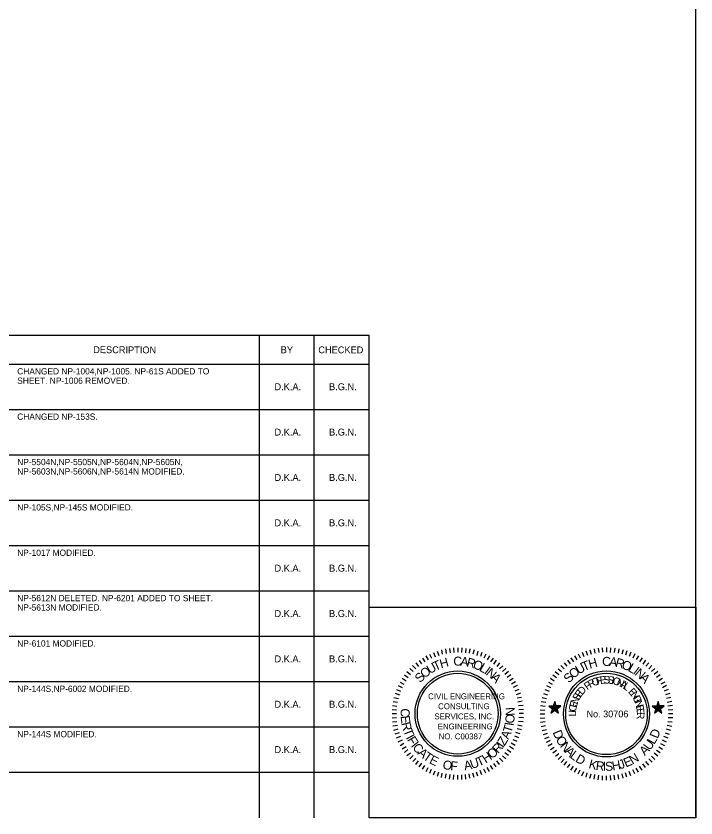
# Model space of a CAD drawing. Extents: x 261099 to 262774, y 322332 to 323393.
# Drawn here: x 262340 to 262774, y 322332 to 322845 of the extents above; entities that cross this region are included whole.
import ezdxf

# ---------------------------------------------------------------- set-up
doc = ezdxf.new("R2010")
doc.units = 0
for name, color, linetype in [('Level 1', 7, 'Continuous'), ('Level 3', 7, 'Continuous'), ('RD_SHT_SEAL_KA', 7, 'Continuous'), ('RD_SHT_TX', 7, 'Continuous')]:
    doc.layers.add(name, color=color, linetype=linetype)

msp = doc.modelspace()

# ---------------------------------------------------------------- linework, layer by layer
at = {"layer": 'Level 1'}
msp.add_lwpolyline([(262565.22, 322466.62), (262774.17, 322466.62), (262774.17, 322331.93), (262565.22, 322331.93)], close=True, dxfattribs=at)
at = {"layer": 'Level 3'}
msp.add_line((262774.17, 322332.83), (262774.17, 323381.93), dxfattribs=at)
at = {"layer": 'RD_SHT_SEAL_KA'}
for p, q in [((262619.3, 322440.71), (262619.44, 322437.75)), ((262621.93, 322440.78), (262621.92, 322437.87)), ((262624.55, 322440.66), (262624.36, 322437.77)), ((262627.12, 322440.39), (262626.8, 322437.59)), ((262711.74, 322440.51), (262712.06, 322437.7)), ((262714.33, 322440.78), (262714.49, 322437.92)), ((262717.03, 322440.84), (262716.97, 322438.03)), ((262719.57, 322440.78), (262719.4, 322437.81)), ((262722.32, 322440.57), (262721.94, 322437.65)), ((262601.58, 322435.55), (262602.98, 322433.01)), ((262603.97, 322436.67), (262605.22, 322434.11)), ((262606.44, 322437.8), (262607.49, 322435.06)), ((262608.87, 322438.62), (262609.77, 322435.87)), ((262611.45, 322439.39), (262612.06, 322436.6)), ((262614.06, 322440.02), (262614.53, 322437.14)), ((262616.7, 322440.35), (262617.04, 322437.56)), ((262629.74, 322440.01), (262629.26, 322437.27)), ((262632.35, 322439.37), (262631.62, 322436.56)), ((262634.86, 322438.67), (262634.02, 322435.89)), ((262637.32, 322437.75), (262636.39, 322435.1)), ((262639.8, 322436.68), (262638.6, 322434.04)), ((262642.14, 322435.53), (262640.7, 322433.07)), ((262696.51, 322435.65), (262697.97, 322433.06)), ((262698.94, 322436.84), (262700.18, 322434.25)), ((262701.37, 322437.92), (262702.45, 322435.17)), ((262703.85, 322438.78), (262704.82, 322436.08)), ((262706.39, 322439.54), (262707.14, 322436.73)), ((262709.09, 322440.13), (262709.57, 322437.22)), ((262724.97, 322440.13), (262724.42, 322437.32)), ((262727.56, 322439.54), (262726.8, 322436.73)), ((262730.09, 322438.84), (262729.23, 322436.03)), ((262732.63, 322437.92), (262731.55, 322435.22)), ((262735.01, 322436.84), (262733.77, 322434.19)), ((262737.39, 322435.65), (262736.04, 322433.17)), ((262595.12, 322431.17), (262596.91, 322428.79)), ((262597.17, 322432.69), (262598.79, 322430.44)), ((262599.41, 322434.13), (262600.9, 322431.78)), ((262644.48, 322434.1), (262642.88, 322431.71)), ((262646.58, 322432.8), (262644.88, 322430.35)), ((262648.66, 322431.05), (262646.93, 322428.82)), ((262689.92, 322431.17), (262691.75, 322428.9)), ((262692.02, 322432.74), (262693.75, 322430.42)), ((262694.29, 322434.25), (262695.8, 322431.87)), ((262739.76, 322434.25), (262738.19, 322431.82)), ((262741.92, 322432.79), (262740.25, 322430.36)), ((262744.03, 322431.17), (262742.19, 322428.96)), ((262589.39, 322425.5), (262591.71, 322423.63)), ((262591.27, 322427.41), (262593.42, 322425.48)), ((262593.04, 322429.34), (262595.13, 322427.26)), ((262650.67, 322429.29), (262648.69, 322427.26)), ((262652.65, 322427.49), (262650.44, 322425.5)), ((262654.27, 322425.5), (262652.09, 322423.62)), ((262684.25, 322425.5), (262686.52, 322423.67)), ((262686.09, 322427.39), (262688.19, 322425.5)), ((262687.87, 322429.39), (262689.97, 322427.23)), ((262746.02, 322429.39), (262744.14, 322427.28)), ((262747.97, 322427.5), (262745.81, 322425.5)), ((262749.7, 322425.5), (262747.48, 322423.67)), ((262586.35, 322421.24), (262588.85, 322419.69)), ((262587.87, 322423.37), (262590.13, 322421.68)), ((262655.92, 322423.36), (262653.56, 322421.68)), ((262657.42, 322421.2), (262655, 322419.7)), ((262681.17, 322421.23), (262683.65, 322419.62)), ((262682.63, 322423.39), (262685.06, 322421.67)), ((262751.26, 322423.39), (262748.99, 322421.72)), ((262752.83, 322421.18), (262750.4, 322419.67)), ((262583.84, 322416.57), (262586.41, 322415.37)), ((262585.08, 322418.85), (262587.44, 322417.54)), ((262658.85, 322418.96), (262656.25, 322417.47)), ((262659.9, 322416.55), (262657.44, 322415.35)), ((262678.58, 322416.54), (262681.17, 322415.29)), ((262679.82, 322418.86), (262682.36, 322417.51)), ((262754.18, 322418.86), (262751.69, 322417.45)), ((262755.31, 322416.54), (262752.77, 322415.24)), ((262581.85, 322411.63), (262584.68, 322410.76)), ((262582.8, 322414.13), (262585.4, 322413.04)), ((262660.94, 322414.15), (262658.32, 322413.08)), ((262661.93, 322411.67), (262659.17, 322410.76)), ((262676.64, 322411.52), (262679.39, 322410.65)), ((262677.55, 322414.05), (262680.25, 322412.97)), ((262756.45, 322414.11), (262753.75, 322413.02)), ((262757.37, 322411.57), (262754.61, 322410.65)), ((262580.56, 322406.48), (262583.42, 322405.98)), ((262581.17, 322409.05), (262583.95, 322408.28)), ((262662.66, 322409.04), (262659.83, 322408.46)), ((262663.16, 322406.53), (262660.37, 322405.92)), ((262675.34, 322406.38), (262678.2, 322405.9)), ((262675.88, 322408.97), (262678.74, 322408.27)), ((262758.12, 322409.03), (262755.26, 322408.33)), ((262758.72, 322406.44), (262755.8, 322405.84)), ((262579.96, 322401.19), (262582.81, 322401.02)), ((262580.14, 322403.89), (262583.06, 322403.48)), ((262663.71, 322403.92), (262660.71, 322403.54)), ((262663.9, 322401.26), (262660.98, 322401.08)), ((262674.69, 322401.09), (262677.55, 322400.93)), ((262674.91, 322403.74), (262677.77, 322403.42)), ((262759.15, 322403.74), (262756.23, 322403.47)), ((262759.31, 322401.09), (262756.45, 322400.93)), ((262579.94, 322395.97), (262582.82, 322396.18)), ((262579.97, 322398.66), (262582.73, 322398.63)), ((262663.89, 322395.97), (262661, 322396.17)), ((262663.88, 322398.69), (262661.13, 322398.64)), ((262674.64, 322398.44), (262677.5, 322398.44)), ((262674.64, 322395.8), (262677.5, 322395.96)), ((262759.31, 322395.85), (262756.45, 322396.02)), ((262759.42, 322398.44), (262756.55, 322398.5)), ((262580.19, 322393.39), (262583.05, 322393.68)), ((262580.52, 322390.75), (262583.36, 322391.26)), ((262663.17, 322390.7), (262660.35, 322391.25)), ((262663.66, 322393.37), (262660.71, 322393.67)), ((262674.91, 322393.1), (262677.82, 322393.53)), ((262675.29, 322390.51), (262678.09, 322390.99)), ((262758.72, 322390.51), (262755.8, 322391.05)), ((262759.04, 322393.15), (262756.18, 322393.42)), ((262581.18, 322388.12), (262583.88, 322388.87)), ((262581.93, 322385.68), (262584.62, 322386.5)), ((262582.78, 322383.1), (262585.5, 322384.23)), ((262660.98, 322383.21), (262658.32, 322384.21)), ((262661.9, 322385.67), (262659.11, 322386.51)), ((262662.67, 322388.18), (262659.86, 322388.91)), ((262675.93, 322387.86), (262678.69, 322388.57)), ((262676.69, 322385.38), (262679.39, 322386.24)), ((262757.31, 322385.38), (262754.61, 322386.24)), ((262758.12, 322387.92), (262755.26, 322388.67)), ((262583.83, 322380.63), (262586.53, 322381.97)), ((262585.09, 322378.33), (262587.51, 322379.82)), ((262658.72, 322378.34), (262656.16, 322379.73)), ((262659.94, 322380.77), (262657.41, 322381.94)), ((262677.5, 322382.84), (262680.25, 322383.87)), ((262678.63, 322380.36), (262681.22, 322381.65)), ((262679.77, 322377.98), (262682.36, 322379.44)), ((262754.18, 322378.03), (262751.64, 322379.38)), ((262755.37, 322380.36), (262752.77, 322381.65)), ((262756.45, 322382.89), (262753.69, 322383.92)), ((262586.41, 322376.11), (262588.86, 322377.65)), ((262587.93, 322373.8), (262590.12, 322375.61)), ((262655.9, 322373.78), (262653.59, 322375.58)), ((262657.46, 322375.95), (262654.94, 322377.57)), ((262681.22, 322375.71), (262683.55, 322377.22)), ((262682.68, 322373.5), (262685, 322375.22)), ((262751.32, 322373.5), (262748.99, 322375.17)), ((262752.83, 322375.66), (262750.4, 322377.17)), ((262589.44, 322371.83), (262591.68, 322373.6)), ((262591.25, 322369.82), (262593.43, 322371.77)), ((262593.12, 322367.97), (262595.14, 322370.05)), ((262650.71, 322367.95), (262648.66, 322370.08)), ((262652.56, 322369.82), (262650.49, 322371.76)), ((262654.36, 322371.8), (262652.09, 322373.56)), ((262684.3, 322371.44), (262686.57, 322373.23)), ((262686.09, 322369.39), (262688.19, 322371.39)), ((262688.03, 322367.45), (262689.92, 322369.61)), ((262746.08, 322367.5), (262744.08, 322369.67)), ((262747.92, 322369.39), (262745.86, 322371.39)), ((262749.75, 322371.44), (262747.48, 322373.28)), ((262595.14, 322366.14), (262596.87, 322368.37)), ((262597.2, 322364.61), (262598.89, 322366.87)), ((262599.32, 322363.09), (262600.88, 322365.52)), ((262601.65, 322361.74), (262603.02, 322364.18)), ((262642.17, 322361.74), (262640.83, 322364.18)), ((262644.38, 322363.14), (262642.9, 322365.49)), ((262646.58, 322364.61), (262644.93, 322366.82)), ((262648.63, 322366.13), (262646.93, 322368.37)), ((262689.97, 322365.77), (262691.75, 322367.94)), ((262692.08, 322364.16), (262693.81, 322366.42)), ((262694.24, 322362.59), (262695.8, 322365.07)), ((262696.56, 322361.29), (262697.97, 322363.78)), ((262737.39, 322361.29), (262736.04, 322363.78)), ((262739.71, 322362.59), (262738.19, 322365.02)), ((262741.97, 322364.16), (262740.3, 322366.48)), ((262743.97, 322365.72), (262742.19, 322367.94)), ((262604, 322360.51), (262605.19, 322363.23)), ((262606.4, 322359.5), (262607.49, 322362.1)), ((262608.9, 322358.55), (262609.75, 322361.34)), ((262611.48, 322357.87), (262612.07, 322360.66)), ((262614.02, 322357.29), (262614.51, 322360.15)), ((262616.61, 322356.8), (262617.03, 322359.72)), ((262619.31, 322356.61), (262619.47, 322359.54)), ((262621.93, 322356.57), (262621.91, 322359.36)), ((262624.6, 322356.6), (262624.43, 322359.52)), ((262627.11, 322356.84), (262626.78, 322359.74)), ((262629.7, 322357.28), (262629.28, 322360.06)), ((262632.34, 322357.87), (262631.66, 322360.65)), ((262634.86, 322358.56), (262634, 322361.28)), ((262637.39, 322359.51), (262636.31, 322362.2)), ((262639.86, 322360.56), (262638.6, 322363.2)), ((262698.99, 322360.05), (262700.18, 322362.7)), ((262701.31, 322358.97), (262702.5, 322361.67)), ((262703.9, 322358.11), (262704.72, 322360.86)), ((262706.44, 322357.3), (262707.09, 322360.16)), ((262709.04, 322356.76), (262709.57, 322359.67)), ((262711.68, 322356.38), (262712.06, 322359.24)), ((262714.38, 322356.11), (262714.54, 322358.97)), ((262717.03, 322356.06), (262717.03, 322358.92)), ((262719.67, 322356), (262719.51, 322359.02)), ((262722.27, 322356.38), (262721.94, 322359.24)), ((262724.91, 322356.76), (262724.42, 322359.62)), ((262727.56, 322357.35), (262726.91, 322360.16)), ((262730.09, 322358.11), (262729.23, 322360.81)), ((262732.63, 322358.97), (262731.55, 322361.67)), ((262735.12, 322360.11), (262733.87, 322362.7))]:
    msp.add_line(p, q, dxfattribs=at)
for points in [[(262683.92, 322406.38), (262683.01, 322403.52), (262680.09, 322403.52), (262682.47, 322401.74), (262681.49, 322399.04), (262683.98, 322400.77), (262686.3, 322399.04), (262685.38, 322401.79), (262687.76, 322403.57), (262684.84, 322403.57)], [(262683.87, 322405.95), (262683.12, 322403.47), (262680.42, 322403.47), (262682.52, 322401.85), (262681.77, 322399.31), (262683.87, 322400.93), (262686.03, 322399.31), (262685.22, 322401.9), (262687.44, 322403.42), (262684.79, 322403.47)], [(262683.98, 322405.57), (262683.12, 322403.31), (262680.79, 322403.31), (262682.74, 322401.9), (262682.04, 322399.63), (262683.92, 322401.04), (262685.87, 322399.58), (262685.06, 322401.96), (262687.06, 322403.25), (262684.68, 322403.31)], [(262683.98, 322405.19), (262683.22, 322403.2), (262681.17, 322403.14), (262682.9, 322401.96), (262682.25, 322399.96), (262683.87, 322401.2), (262685.65, 322399.96), (262685.06, 322401.96), (262686.68, 322403.25), (262684.57, 322403.14)], [(262683.92, 322404.82), (262683.39, 322403.09), (262681.55, 322403.04), (262683.01, 322402.01), (262682.41, 322400.23), (262683.92, 322401.36), (262685.44, 322400.23), (262684.84, 322402.01), (262686.25, 322403.09), (262684.57, 322403.09)], [(262750.07, 322406.38), (262749.1, 322403.57), (262746.24, 322403.52), (262748.62, 322401.79), (262747.64, 322398.99), (262750.07, 322400.77), (262752.45, 322398.99), (262751.48, 322401.79), (262753.91, 322403.57), (262750.94, 322403.57)], [(262750.02, 322406.01), (262749.21, 322403.47), (262746.57, 322403.42), (262748.78, 322401.79), (262747.97, 322399.31), (262750.07, 322400.82), (262752.24, 322399.31), (262751.42, 322401.85), (262753.59, 322403.47), (262750.89, 322403.42)], [(262750.07, 322405.57), (262749.37, 322403.25), (262746.94, 322403.31), (262748.89, 322401.9), (262748.19, 322399.58), (262750.07, 322401.04), (262752.02, 322399.63), (262751.26, 322401.85), (262753.21, 322403.36), (262750.83, 322403.31)], [(262750.02, 322405.19), (262749.43, 322403.14), (262747.32, 322403.14), (262749.1, 322401.96), (262748.29, 322400.01), (262750.07, 322401.2), (262751.75, 322400.01), (262751.1, 322401.96), (262752.83, 322403.2), (262750.72, 322403.2)], [(262750.02, 322404.77), (262749.48, 322403.04), (262747.64, 322403.09), (262749.1, 322402.07), (262748.62, 322400.23), (262750.02, 322401.31), (262751.48, 322400.28), (262750.99, 322401.96), (262752.5, 322403.04), (262750.62, 322403.09)], [(262683.92, 322404.44), (262683.49, 322402.93), (262681.93, 322402.98), (262683.17, 322402.07), (262682.68, 322400.61), (262683.98, 322401.52), (262685.22, 322400.55), (262684.68, 322402.07), (262685.98, 322402.87), (262684.41, 322402.93)], [(262683.92, 322404.01), (262683.55, 322402.87), (262682.3, 322402.71), (262683.33, 322402.12), (262682.95, 322400.93), (262683.87, 322401.63), (262685, 322400.87), (262684.63, 322402.12), (262685.54, 322402.82), (262684.3, 322402.82)], [(262683.92, 322403.63), (262683.65, 322402.71), (262682.68, 322402.71), (262683.49, 322402.17), (262683.17, 322401.25), (262683.92, 322401.74), (262684.74, 322401.2), (262684.47, 322402.12), (262685.22, 322402.66), (262684.19, 322402.77)], [(262683.92, 322403.2), (262683.71, 322402.6), (262683.01, 322402.6), (262683.55, 322402.17), (262683.44, 322401.58), (262683.98, 322401.96), (262684.41, 322401.52), (262684.3, 322402.17), (262684.84, 322402.55), (262684.14, 322402.6)], [(262683.98, 322402.87), (262683.76, 322402.49), (262683.44, 322402.49), (262683.76, 322402.22), (262683.6, 322401.85), (262683.98, 322402.12), (262684.19, 322401.85), (262684.09, 322402.28), (262684.41, 322402.44), (262684.09, 322402.44)], [(262683.98, 322402.44), (262683.92, 322402.28), (262683.71, 322402.33), (262683.87, 322402.33), (262683.82, 322402.17), (262683.92, 322402.17), (262683.98, 322402.17), (262683.98, 322402.28), (262684.14, 322402.39), (262683.98, 322402.39)], [(262750.13, 322404.39), (262749.59, 322402.98), (262748.02, 322402.98), (262749.32, 322402.12), (262748.78, 322400.55), (262750.07, 322401.47), (262751.26, 322400.61), (262750.89, 322402.01), (262752.02, 322402.93), (262750.56, 322402.98)], [(262750.07, 322404.01), (262749.64, 322402.87), (262748.4, 322402.82), (262749.48, 322402.07), (262749.05, 322400.93), (262750.07, 322401.69), (262751.05, 322400.87), (262750.67, 322402.12), (262751.75, 322402.82), (262750.45, 322402.87)], [(262750.07, 322403.57), (262749.8, 322402.71), (262748.78, 322402.71), (262749.59, 322402.12), (262749.27, 322401.25), (262750.07, 322401.74), (262750.83, 322401.2), (262750.56, 322402.12), (262751.26, 322402.71), (262750.34, 322402.71)], [(262750.07, 322403.25), (262749.75, 322402.6), (262749.21, 322402.55), (262749.7, 322402.22), (262749.48, 322401.58), (262750.07, 322401.9), (262750.62, 322401.52), (262750.4, 322402.12), (262750.99, 322402.55), (262750.34, 322402.6)], [(262750.02, 322402.87), (262749.97, 322402.49), (262749.54, 322402.49), (262749.91, 322402.22), (262749.7, 322401.85), (262750.13, 322402.07), (262750.4, 322401.85), (262750.24, 322402.17), (262750.62, 322402.49), (262750.24, 322402.44)], [(262750.13, 322402.44), (262750.07, 322402.33), (262749.91, 322402.33), (262749.97, 322402.28), (262749.97, 322402.12), (262750.02, 322402.22), (262750.18, 322402.22), (262750.13, 322402.28), (262750.18, 322402.33), (262750.07, 322402.28)]]:
    msp.add_lwpolyline(points, close=True, dxfattribs=at)
for radius in [27.48, 26.04]:
    msp.add_circle((262716.99, 322398.45), radius, dxfattribs=at)
for major_axis in [(0.01, 27.28), (0.01, 25.84)]:
    msp.add_ellipse((262621.9, 322398.63), major_axis=major_axis, ratio=0.998589, dxfattribs=at)
at = {"layer": 'RD_SHT_TX'}
for p, q in [((262254.62, 322640.63), (262565.22, 322640.63)), ((262495.22, 322331.93), (262495.22, 322640.63)), ((262530.22, 322331.93), (262530.22, 322640.63)), ((262565.22, 322360.93), (262565.22, 322640.63)), ((262565.22, 322621.93), (261944.02, 322621.93)), ((262565.22, 322592.93), (261944.02, 322592.93)), ((262565.22, 322592.93), (261944.02, 322592.93)), ((262565.22, 322563.93), (261944.02, 322563.93)), ((262565.22, 322534.93), (261944.02, 322534.93)), ((262565.22, 322505.93), (261944.02, 322505.93)), ((262565.22, 322476.93), (261944.02, 322476.93)), ((262565.22, 322447.93), (261944.02, 322447.93)), ((262565.22, 322418.93), (261944.02, 322418.93)), ((262565.22, 322389.93), (261944.02, 322389.93)), ((262565.22, 322360.93), (261944.02, 322360.93))]:
    msp.add_line(p, q, dxfattribs=at)

# ---------------------------------------------------------------- texts
at = {"layer": 'RD_SHT_SEAL_KA'}
for s, height, rotation, p in [('U', 5.79, 30.8031, (262604.14, 322423.76)), ('T', 5.79, 23.2887, (262607.57, 322425.86)), ('H', 5.79, 15.7743, (262611.26, 322427.5)), ('C', 5.79, 0.6858, (262619.14, 322429.28)), ('A', 5.79, 352.8136, (262623.36, 322429.37)), ('R', 5.79, 345.657, (262627.18, 322428.94)), ('O', 5.79, 338.1426, (262631.1, 322427.99)), ('L', 5.79, 329.9125, (262635.21, 322426.37)), ('U', 5.79, 30.8031, (262699.23, 322423.57)), ('T', 5.79, 23.2887, (262702.67, 322425.68)), ('H', 5.79, 15.7743, (262706.35, 322427.32)), ('C', 5.79, 0.6858, (262714.24, 322429.09)), ('A', 5.79, 352.8136, (262718.46, 322429.18)), ('R', 5.79, 345.657, (262722.28, 322428.76)), ('O', 5.79, 338.1426, (262726.19, 322427.81)), ('L', 5.79, 329.9125, (262730.3, 322426.19)), ('O', 5.79, 39.0332, (262600.72, 322420.96)), ('I', 5.79, 323.1138, (262638.4, 322424.6)), ('N', 5.79, 320.609, (262639.52, 322423.86)), ('O', 5.79, 39.0332, (262695.82, 322420.77)), ('I', 5.79, 323.1138, (262733.49, 322424.42)), ('N', 5.79, 320.609, (262734.61, 322423.67)), ('S', 5.79, 46.5476, (262597.99, 322417.99)), ('A', 5.79, 313.0946, (262642.66, 322421.34)), ('S', 5.79, 46.5476, (262693.08, 322417.81)), ('R', 4.82, 28.555, (262706.54, 322414.88)), ('O', 4.82, 21.7793, (262708.55, 322415.99)), ('F', 4.82, 14.3582, (262710.89, 322416.93)), ('E', 4.82, 7.9051, (262713.01, 322417.5)), ('S', 4.82, 1.452, (262715.17, 322417.82)), ('S', 4.82, 354.6762, (262717.47, 322417.9)), ('I', 4.82, 347.9004, (262719.76, 322417.7)), ('O', 4.82, 345.6418, (262720.52, 322417.58)), ('N', 4.82, 338.2207, (262722.96, 322416.96)), ('A', 5.79, 313.0946, (262737.76, 322421.15)), ('D', 4.82, 48.9361, (262701.47, 322410.22)), ('P', 4.82, 35.3308, (262704.67, 322413.54)), ('A', 4.82, 331.445, (262725.1, 322416.12)), ('L', 4.82, 324.9919, (262727.04, 322415.09)), ('E', 4.82, 312.0319, (262730.52, 322412.41)), ('CIVIL ENGINEERING', 3.7513, 359.9897, (262603, 322407.83)), ('N', 4.82, 68.9407, (262698.37, 322404.21)), ('S', 4.82, 62.165, (262699.18, 322406.36)), ('E', 4.82, 55.3892, (262700.24, 322408.41)), ('N', 4.82, 305.5788, (262732, 322410.8)), ('G', 4.82, 298.803, (262733.35, 322408.93)), ('CONSULTING', 3.751, 359.9897, (262609.38, 322401.48)), ('C', 4.82, 82.4923, (262697.54, 322399.69)), ('E', 4.82, 75.3939, (262697.84, 322402.08)), ('I', 4.82, 291.7046, (262734.52, 322406.83)), ('N', 4.82, 289.446, (262734.84, 322406.13)), ('E', 4.82, 282.6702, (262735.62, 322403.97)), ('C', 5.79, 268.515, (262585.52, 322402.08)), ('N', 5.79, 91.8428, (262658.42, 322397.3)), ('L', 4.82, 90.8813, (262697.56, 322396.85)), ('I', 4.82, 84.7509, (262697.5, 322398.93)), ('E', 4.82, 276.2171, (262736.13, 322401.83)), ('E', 5.79, 276.3872, (262585.39, 322397.07)), ('SERVICES, INC.', 3.7513, 359.9897, (262606.99, 322395)), ('O', 5.79, 83.6128, (262657.85, 322392.09)), ('R', 4.82, 269.764, (262736.39, 322399.66)), ('R', 5.79, 283.5438, (262585.87, 322392.53)), ('T', 5.79, 291.0582, (262586.97, 322387.87)), ('ENGINEERING', 3.7513, 359.9897, (262609.13, 322388.56)), ('T', 5.79, 73.5935, (262656.16, 322385.93)), ('I', 5.79, 81.108, (262657.53, 322390.52)), ('I', 5.79, 298.5727, (262588.68, 322383.4)), ('F', 5.79, 301.0775, (262589.38, 322381.96)), ('NO. C00387', 3.751, 359.9897, (262609.74, 322382.19)), ('Z', 5.79, 58.9225, (262651.83, 322377.67)), ('A', 5.79, 66.437, (262654.32, 322381.76)), ('D', 5.78, 292.563, (262682.48, 322386.7)), ('O', 5.78, 300.0892, (262684.32, 322382.28)), ('D', 5.78, 67.437, (262749.67, 322382.28)), ('I', 5.79, 308.234, (262591.71, 322378.04)), ('C', 5.79, 310.7388, (262592.64, 322376.74)), ('R', 5.79, 48.9033, (262647.73, 322372.78)), ('I', 5.79, 56.4177, (262650.89, 322376.38)), ('N', 5.78, 308.3321, (262686.97, 322377.76)), ('U', 5.78, 53.1014, (262744.65, 322374.7)), ('L', 5.78, 60.6276, (262747.52, 322378.52)), ('A', 5.79, 318.6111, (262595.91, 322372.94)), ('T', 5.79, 325.7677, (262599.32, 322369.9)), ('H', 5.79, 33.1588, (262639.74, 322366.74)), ('O', 5.79, 40.6733, (262643.76, 322369.35)), ('A', 5.78, 315.8583, (262689.94, 322374.01)), ('L', 5.78, 323.0261, (262693.2, 322370.82)), ('A', 5.78, 45.9336, (262741.47, 322371.43)), ('E', 5.79, 333.2821, (262603.27, 322367.19)), ('O', 5.79, 348.0127, (262611.88, 322363.49)), ('A', 5.79, 10.9734, (262626.38, 322362.37)), ('U', 5.79, 18.13, (262630.86, 322363.21)), ('T', 5.79, 25.6444, (262635.42, 322364.68)), ('D', 5.78, 329.8355, (262696.65, 322368.2)), ('K', 5.78, 344.9476, (262705.24, 322363.94)), ('H', 5.78, 10.0349, (262720.98, 322362.21)), ('J', 5.78, 17.5611, (262725.69, 322363.04)), ('E', 5.78, 23.6537, (262729.4, 322364.17)), ('N', 5.78, 30.8215, (262733.58, 322365.98)), ('F', 5.79, 356.2428, (262617.01, 322362.42)), ('R', 5.78, 352.4738, (262709.86, 322362.7)), ('I', 5.78, 360, (262714.6, 322362.07)), ('S', 5.78, 2.5087, (262716.2, 322362))]:
    msp.add_text(s, height=height, rotation=rotation, dxfattribs=at).set_placement(p)
msp.add_text('No. 30706', height=4.336, dxfattribs=at).set_placement((262704.22, 322396.27))
at = {"layer": 'RD_SHT_TX'}
for s, height, rotation, p in [('DESCRIPTION', 4.4083, 359.7246, (262388.92, 322629.17)), ('BY', 4.408, 359.7246, (262508.77, 322629.09)), ('CHANGED NP-1004,NP-1005. NP-61S ADDED TO', 4, 360, (262340.37, 322615.54)), ('SHEET. NP-1006 REMOVED.', 4, 360, (262340.37, 322609.54)), ('D.K.A.', 4.4, 360, (262504.81, 322605.46)), ('B.G.N.', 4.4, 360, (262539.68, 322605.46)), ('CHANGED NP-153S.', 4, 360, (262340.37, 322586.54)), ('D.K.A.', 4.4, 360, (262504.81, 322576.46)), ('B.G.N.', 4.4, 360, (262539.68, 322576.46)), ('NP-5504N,NP-5505N,NP-5604N,NP-5605N,', 4, 360, (262340.37, 322557.54)), ('NP-5603N,NP-5606N,NP-5614N MODIFIED.', 4, 360, (262340.37, 322551.54)), ('D.K.A.', 4.4, 360, (262504.81, 322547.46)), ('B.G.N.', 4.4, 360, (262539.68, 322547.46)), ('NP-105S,NP-145S MODIFIED.', 4, 360, (262340.37, 322528.54)), ('D.K.A.', 4.4, 360, (262504.81, 322518.46)), ('B.G.N.', 4.4, 360, (262539.68, 322518.46)), ('NP-1017 MODIFIED.', 4, 360, (262340.37, 322499.54)), ('D.K.A.', 4.4, 360, (262504.81, 322489.46)), ('B.G.N.', 4.4, 360, (262539.68, 322489.46)), ('NP-5612N DELETED. NP-6201 ADDED TO SHEET.', 4, 360, (262340.37, 322470.54)), ('NP-5613N MODIFIED.', 4, 360, (262340.37, 322464.54)), ('D.K.A.', 4.4, 360, (262504.81, 322460.46)), ('B.G.N.', 4.4, 360, (262539.68, 322460.46)), ('NP-6101 MODIFIED.', 4, 360, (262340.37, 322441.54)), ('D.K.A.', 4.4, 360, (262504.81, 322431.46)), ('B.G.N.', 4.4, 360, (262539.68, 322431.46)), ('NP-144S,NP-6002 MODIFIED.', 4, 360, (262340.37, 322412.54)), ('D.K.A.', 4.4, 360, (262504.81, 322402.46)), ('B.G.N.', 4.4, 360, (262539.68, 322402.46)), ('NP-144S MODIFIED.', 4, 360, (262340.37, 322383.54)), ('D.K.A.', 4.4, 360, (262504.81, 322373.46)), ('B.G.N.', 4.4, 360, (262539.68, 322373.46))]:
    msp.add_text(s, height=height, rotation=rotation, dxfattribs=at).set_placement(p)
msp.add_text('CHECKED', height=4.4, dxfattribs=at).set_placement((262532.82, 322629.05))

doc.saveas('drawing.dxf')
